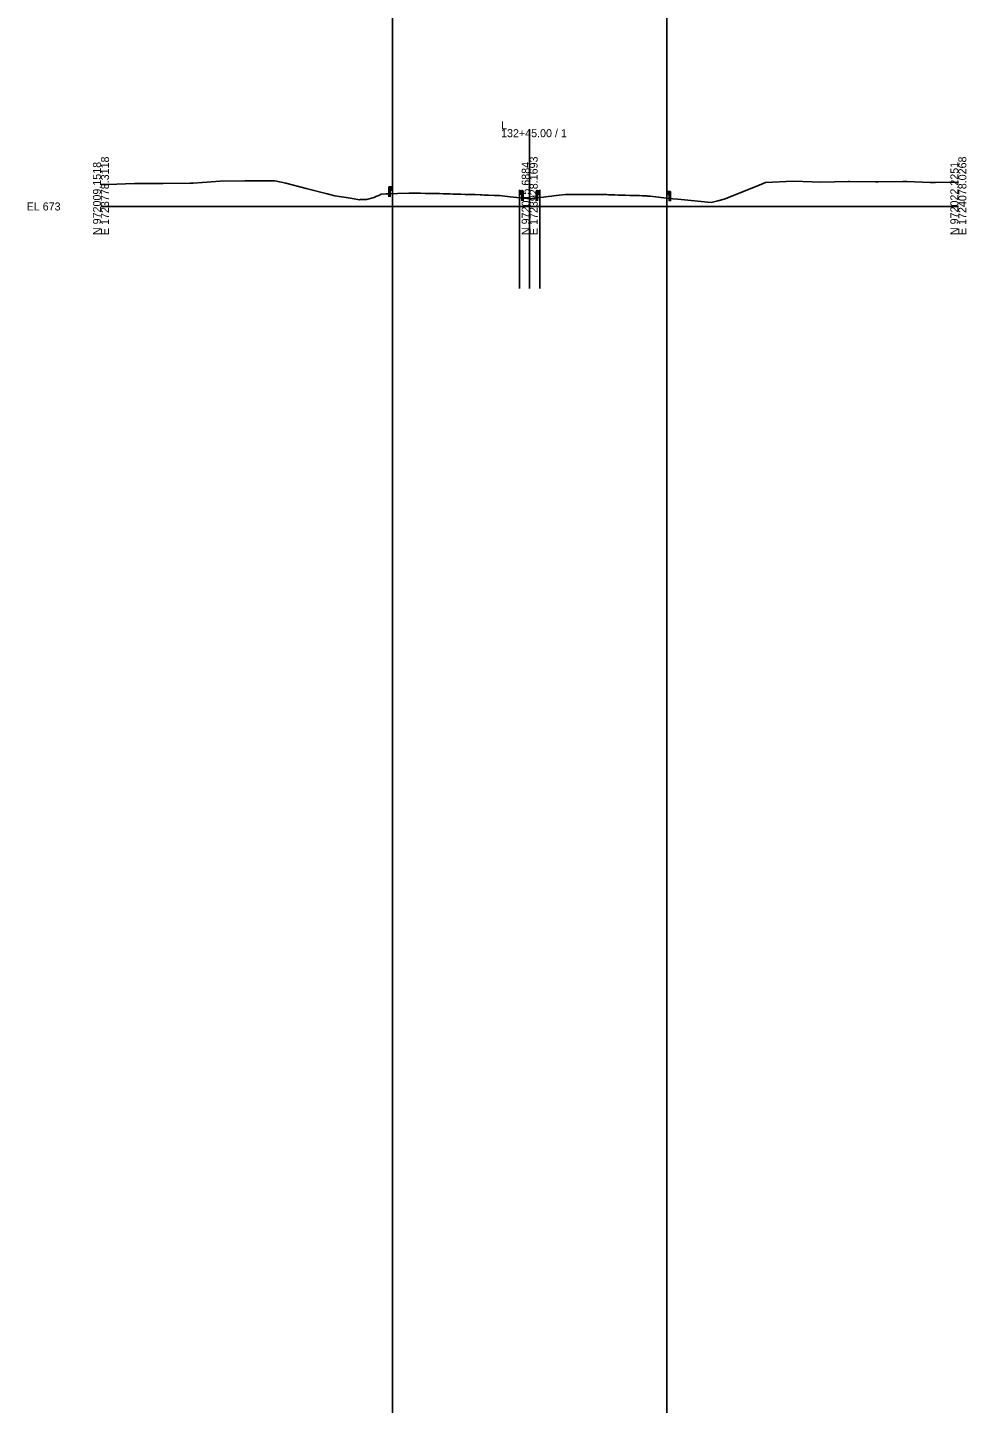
# Model space of a CAD drawing. Extents: x -26 to 303, y -29 to 15026.
# Drawn here: x -25.7 to 302.8, y 13581.1 to 14062.6 of the extents above; entities that cross this region are included whole.
import ezdxf

# ---------------------------------------------------------------- set-up
doc = ezdxf.new("R2010")
doc.units = 0
for name, color, linetype in [('Exist Cross Section Cell', 7, 'Continuous'), ('Exist XS Center Line Elevation Label', 7, 'Continuous'), ('Exist XS Ground Line', 7, 'Continuous'), ('Scratch_Level_0', 7, 'Continuous'), ('Typical Guardrail CELL', 7, 'Continuous')]:
    doc.layers.add(name, color=color, linetype=linetype)

msp = doc.modelspace()

# ---------------------------------------------------------------- linework, layer by layer
at = {"layer": 'Exist Cross Section Cell'}
for p, q in [((150, 14000), (150, 14027.06)), ((0, 14000), (150, 14000)), ((150, 14000), (300, 14000))]:
    msp.add_line(p, q, dxfattribs=at)
at = {"layer": 'Exist XS Ground Line'}
msp.add_lwpolyline([(0, 14007.66), (1.7, 14007.69), (2.44, 14007.72), (11.71, 14008.03), (12.03, 14008.03), (19.35, 14008.06), (21.72, 14008.08), (31.21, 14008.18), (31.73, 14008.18), (32.29, 14008.17), (41.74, 14008.83), (50.39, 14009), (51.75, 14009.02), (58.12, 14008.97), (60.82, 14009.01), (64.68, 14008.17), (71.77, 14006.25), (79.17, 14004.4), (81.78, 14003.78), (87.37, 14002.87), (90.44, 14002.38), (90.87, 14002.39), (92.91, 14002.43), (95.6, 14003.18), (96.18, 14003.46), (97.22, 14003.85), (98.01, 14004.34), (99.76, 14004.4), (100.79, 14004.43), (103.78, 14004.54), (107.67, 14004.69), (108.5, 14004.68), (109.24, 14004.68), (110.91, 14004.66), (111.4, 14004.66), (111.82, 14004.65), (113.41, 14004.59), (114.41, 14004.57), (115.91, 14004.54), (117.28, 14004.52), (118.41, 14004.49), (119.69, 14004.45), (120.9, 14004.41), (122.18, 14004.38), (123.12, 14004.36), (124.83, 14004.32), (125.89, 14004.29), (127.45, 14004.25), (128.39, 14004.22), (130.06, 14004.17), (130.89, 14004.14), (132.7, 14004.08), (133.39, 14004.05), (134.24, 14004.02), (135.64, 14003.96), (137.66, 14003.88), (138.43, 14003.85), (138.87, 14003.83), (139.47, 14003.81), (143.2, 14003.41), (149.08, 14002.8), (149.83, 14002.72), (154.9, 14003.27), (156.45, 14003.45), (157.65, 14003.6), (159.31, 14003.81), (162.52, 14004.2), (163.71, 14004.21), (164.26, 14004.22), (165.32, 14004.21), (165.96, 14004.21), (167.64, 14004.21), (168.47, 14004.21), (169.37, 14004.2), (170.95, 14004.2), (172.44, 14004.19), (173.47, 14004.18), (174.57, 14004.18), (175.96, 14004.17), (176.58, 14004.15), (177.06, 14004.14), (177.6, 14004.12), (178.45, 14004.1), (179.78, 14004.05), (180.93, 14004.01), (181.99, 14003.99), (183.44, 14003.96), (185.02, 14003.9), (185.94, 14003.87), (186.77, 14003.84), (188.45, 14003.8), (189.32, 14003.77), (189.73, 14003.75), (190.96, 14003.69), (191.36, 14003.67), (191.83, 14003.65), (192.17, 14003.63), (198.97, 14002.85), (199.52, 14002.79), (200.06, 14002.73), (201.82, 14002.57), (213.48, 14001.34), (215.85, 14001.96), (218.02, 14002.6), (229.48, 14007.1), (232.51, 14008.35), (242.21, 14008.83), (248.82, 14008.62), (251.93, 14008.53), (261.39, 14008.74), (261.94, 14008.74), (270.98, 14008.68), (271.95, 14008.67), (280.57, 14008.8), (281.95, 14008.75), (290.16, 14008.41), (291.96, 14008.44), (300, 14008.48)], dxfattribs=at)
at = {"layer": 'Scratch_Level_0'}
for p, q in [((102, 15009.56), (102, -28.7)), ((198, 15009.56), (198, -28.7)), ((146.39, 14005.88), (146.39, 13971.3)), ((153.61, 14005.88), (153.61, 13971.3)), ((150, 14000), (150, 13971.3))]:
    msp.add_line(p, q, dxfattribs=at)
at = {"layer": 'Typical Guardrail CELL'}
for p, q in [((101.18, 14006.92), (100.68, 14006.92)), ((100.68, 14006.92), (100.68, 14004.43)), ((101.18, 14004.43), (100.68, 14004.43)), ((100.68, 14004.43), (100.68, 14003.42)), ((101.18, 14006.92), (101.18, 14004.43)), ((101.18, 14006.92), (101.68, 14006.92)), ((101.18, 14005.76), (101.68, 14005.76)), ((101.18, 14004.43), (101.18, 14003.42)), ((101.68, 14006.92), (101.68, 14005.76)), ((101.68, 14006.92), (101.97, 14006.71)), ((101.68, 14006.38), (101.97, 14006.59)), ((101.68, 14006.34), (101.68, 14006.38)), ((101.68, 14006.34), (101.68, 14006.29)), ((101.68, 14006.29), (101.97, 14006.09)), ((101.68, 14005.76), (101.97, 14005.96)), ((146.71, 14005.43), (146.42, 14005.22)), ((146.71, 14004.89), (146.42, 14005.1)), ((146.71, 14004.8), (146.42, 14004.6)), ((146.71, 14004.27), (146.42, 14004.47)), ((147.21, 14005.43), (146.71, 14005.43)), ((146.71, 14005.43), (146.71, 14004.27)), ((146.71, 14004.85), (146.71, 14004.89)), ((146.71, 14004.85), (146.71, 14004.8)), ((147.21, 14004.27), (146.71, 14004.27)), ((147.21, 14005.43), (147.21, 14002.94)), ((147.21, 14005.43), (147.71, 14005.43)), ((147.71, 14005.43), (147.71, 14002.94)), ((152.79, 14005.47), (152.29, 14005.47)), ((152.29, 14005.47), (152.29, 14002.99)), ((152.79, 14005.47), (152.79, 14002.99)), ((152.79, 14005.47), (153.29, 14005.47)), ((152.79, 14004.31), (153.29, 14004.31)), ((153.29, 14005.47), (153.29, 14004.31)), ((153.29, 14005.47), (153.58, 14005.27)), ((153.29, 14004.94), (153.58, 14005.14)), ((153.29, 14004.89), (153.29, 14004.94)), ((153.29, 14004.89), (153.29, 14004.85)), ((153.29, 14004.85), (153.58, 14004.64)), ((153.29, 14004.31), (153.58, 14004.52)), ((198.32, 14005.3), (198.03, 14005.1)), ((198.32, 14004.77), (198.03, 14004.97)), ((198.32, 14004.67), (198.03, 14004.47)), ((198.32, 14004.14), (198.03, 14004.34)), ((198.82, 14005.3), (198.32, 14005.3)), ((198.32, 14005.3), (198.32, 14004.14)), ((198.32, 14004.72), (198.32, 14004.77)), ((198.32, 14004.72), (198.32, 14004.67)), ((198.82, 14004.14), (198.32, 14004.14)), ((198.82, 14005.3), (198.82, 14002.82)), ((198.82, 14005.3), (199.32, 14005.3)), ((199.32, 14005.3), (199.32, 14002.82)), ((147.21, 14002.94), (147.71, 14002.94)), ((147.21, 14002.94), (147.21, 14001.93)), ((147.71, 14002.94), (147.71, 14001.93)), ((152.79, 14002.99), (152.29, 14002.99)), ((152.29, 14002.99), (152.29, 14001.98)), ((152.79, 14002.99), (152.79, 14001.98)), ((198.82, 14002.82), (199.32, 14002.82)), ((198.82, 14002.82), (198.82, 14001.81)), ((199.32, 14002.82), (199.32, 14001.81))]:
    msp.add_line(p, q, dxfattribs=at)
for centre, start, end in [((101.92, 14006.65), 304.9888, 54.997), ((101.92, 14006.02), 304.9634, 54.9941), ((146.47, 14005.16), 125.003, 235.0112), ((146.47, 14004.53), 125.0059, 235.0366), ((153.53, 14005.21), 304.9888, 54.997), ((153.53, 14004.58), 304.9634, 54.9941), ((198.08, 14005.03), 125.003, 235.0112), ((198.08, 14004.41), 125.0059, 235.0366)]:
    msp.add_arc(centre, 0.0776, start, end, dxfattribs=at)

# ---------------------------------------------------------------- texts
at = {"layer": 'Exist Cross Section Cell'}
for s, p in [('L', (140, 14027.06)), ('132+45.00 / 1', (140, 14024.26)), ('EL 673', (-26, 13998.6))]:
    msp.add_text(s, height=2.8, dxfattribs=at).set_placement(p)
for s, p in [('N 972009.1518', (0, 13990)), ('E 1723778.3118', (2.8, 13990)), ('N 972015.6884', (150, 13990)), ('E 1723928.1693', (152.8, 13990)), ('N 972022.2251', (300, 13990)), ('E 1724078.0268', (302.8, 13990))]:
    msp.add_text(s, height=2.8, rotation=90, dxfattribs=at).set_placement(p)
at = {"layer": 'Exist XS Center Line Elevation Label'}
msp.add_text('675.74', height=0.18, dxfattribs=at).set_placement((149.61, 14002.25))

doc.saveas('drawing.dxf')
